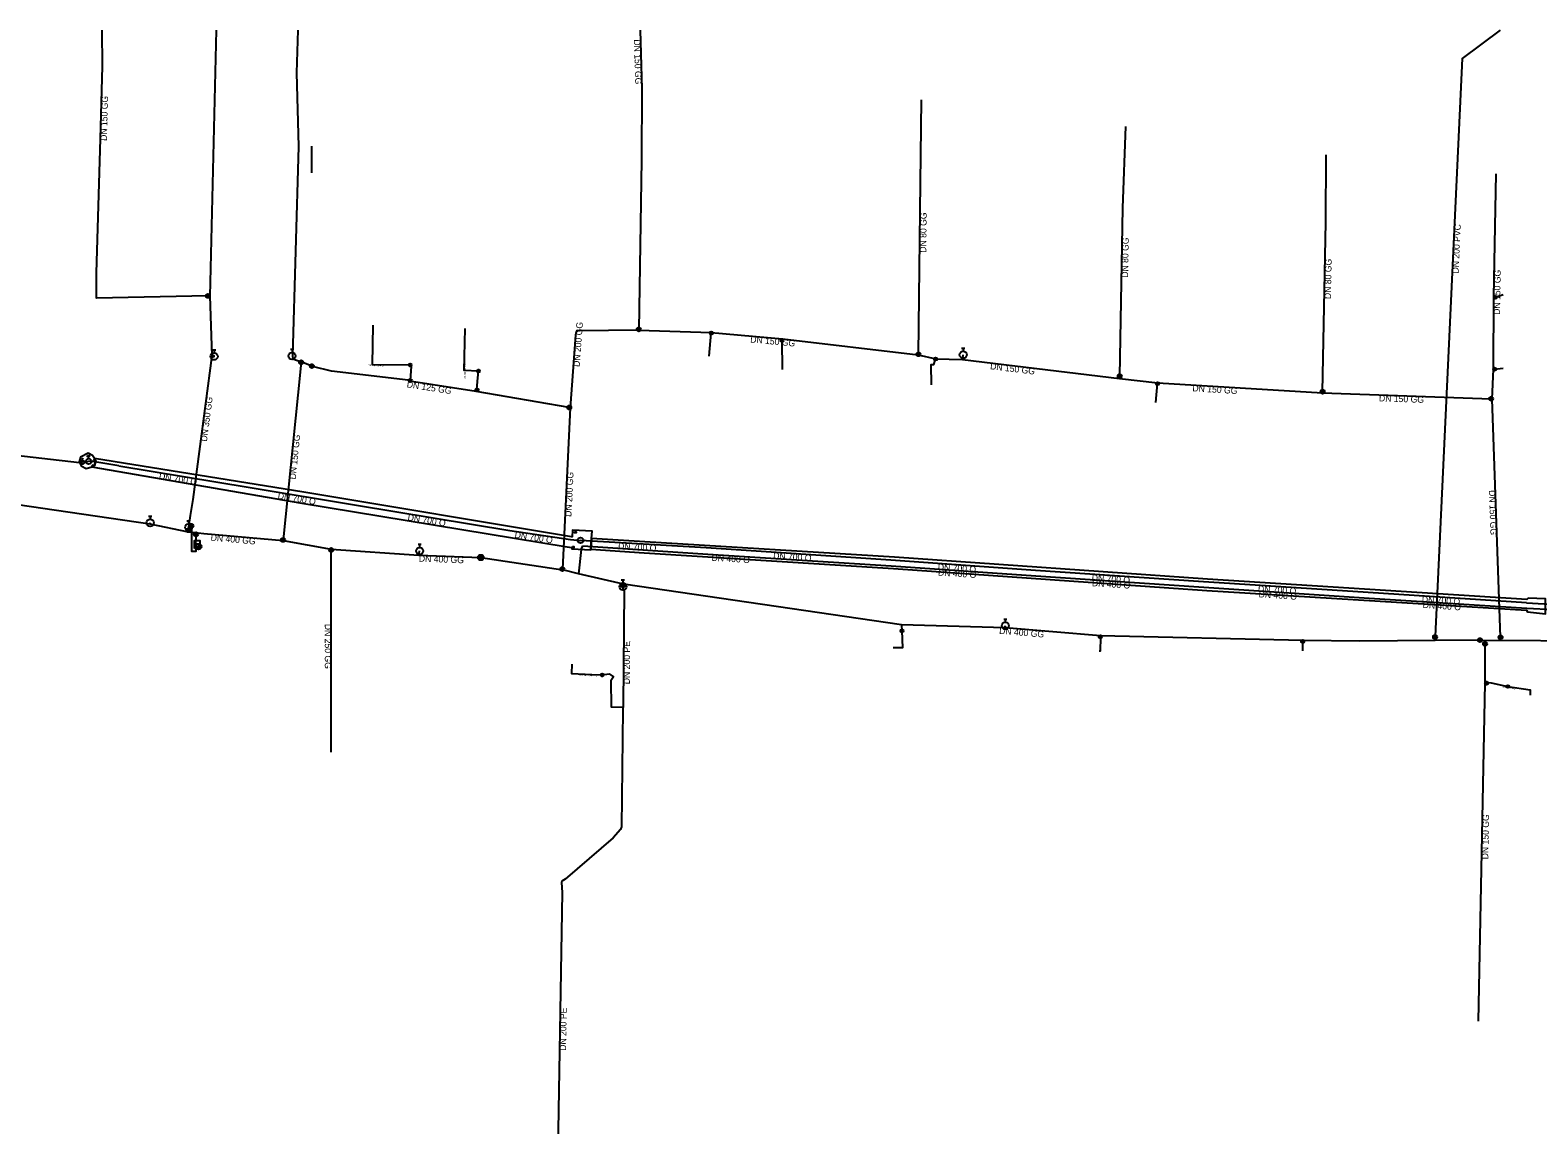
# Model space of a CAD drawing. Extents: x -451355 to -449353, y -1101368 to -1101089.
# Drawn here: x -450784.4 to -450409.1, y -1101364 to -1101089.2 of the extents above; entities that cross this region are included whole.
import ezdxf

# ---------------------------------------------------------------- set-up
doc = ezdxf.new("R2010")
doc.units = 0
for name, color, linetype in [('_hydrantova_odbocka_', 7, 'Continuous'), ('_kolektor_', 7, 'Continuous'), ('_pripojka_prevzato_z_dokumentace_', 7, 'Continuous'), ('_pripojka_priblizne_', 7, 'Continuous'), ('_sachta_voda_', 7, 'Continuous'), ('_voda_smvak_prevzato_z_dokumentace_', 7, 'Continuous'), ('_voda_smvak_priblizne_', 7, 'Continuous'), ('Default', 7, 'Continuous'), ('MoLevel 27', 7, 'Continuous'), ('MoLevel 28', 7, 'Continuous'), ('MoLevel 30', 7, 'Continuous'), ('MoLevel 38', 7, 'Continuous'), ('MoLevel 42', 7, 'Continuous'), ('MoLevel 46', 7, 'Continuous'), ('MoLevel 53', 7, 'Continuous'), ('MoLevel 55', 7, 'Continuous')]:
    doc.layers.add(name, color=color, linetype=linetype)

# ---------------------------------------------------------------- blocks, each defined once
blk = doc.blocks.new('_uzaver_')
at = {"layer": 'Default'}
for p, q in [((-0.000035, -0.000035), (0.000035, 0.000035)), ((0.000035, -0.000035), (-0.000035, 0.000035))]:
    blk.add_line(p, q, dxfattribs=at)
for radius in [0.00005, 0.0000025]:
    blk.add_circle((0, 0), radius, dxfattribs=at)
blk = doc.blocks.new('_uzaver_pripojka_')
at = {"layer": 'Default'}
for p, q in [((-0.000035, -0.000035), (0.000035, 0.000035)), ((0.000035, -0.000035), (-0.000035, 0.000035))]:
    blk.add_line(p, q, dxfattribs=at)
for radius in [0.00005, 0.0000025]:
    blk.add_circle((0, 0), radius, dxfattribs=at)
blk = doc.blocks.new('_hydrant_voda_')
at = {"layer": 'Default'}
for p, q in [((-0.000023, 0.000095), (0.000023, 0.000095)), ((0, 0.000095), (0, 0.00005))]:
    blk.add_line(p, q, dxfattribs=at)
blk.add_circle((0, 0), 0.00005, dxfattribs=at)
blk = doc.blocks.new('_vzdusnik_')
at = {"layer": 'Default'}
blk.add_line((0, 0.000095), (0.00001, 0.00008), dxfattribs=at)
blk.add_lwpolyline([(0, 0.00005), (0, 0.000095), (-0.00001, 0.00008)], dxfattribs=at)
blk.add_circle((0, 0), 0.00005, dxfattribs=at)
blk = doc.blocks.new('_sachta_voda_')
at = {"layer": 'Default'}
blk.add_circle((0, 0), 0.000035, dxfattribs=at)
blk = doc.blocks.new('_poklop_voda_')
at = {"layer": 'Default'}
blk.add_lwpolyline([(-0.00002, 0.000015), (0.00002, 0.000015), (0.00002, -0.000015), (-0.00002, -0.000015), (-0.00002, 0.000015)], dxfattribs=at)

msp = doc.modelspace()

# ---------------------------------------------------------------- linework, layer by layer
at = {"layer": '_hydrantova_odbocka_'}
msp.add_line((-450719.15, -1101170.31), (-450719.24, -1101170.31), dxfattribs=at)
for points in [[(-450738.63, -1101170.42), (-450738.92, -1101170.36), (-450739.22, -1101170.23)], [(-450552.32, -1101171.15), (-450552.27, -1101170.83), (-450552.17, -1101170.01)], [(-450754.63, -1101212.14), (-450754.55, -1101211.85), (-450754.55, -1101211.85)], [(-450687.71, -1101219.89), (-450687.6, -1101219.54), (-450687.47, -1101218.86)], [(-450541.73, -1101238), (-450541.69, -1101237.49), (-450541.69, -1101237.49), (-450541.69, -1101237.49), (-450541.69, -1101237.49), (-450541.69, -1101237.49), (-450541.69, -1101237.49), (-450541.69, -1101237.49), (-450541.69, -1101237.49), (-450541.69, -1101237.49)]]:
    msp.add_lwpolyline(points, dxfattribs=at)
at = {"layer": '_kolektor_'}
for points in [[(-450772.25, -1101196.65), (-450771.74, -1101197.69), (-450770.49, -1101198.33), (-450769.08, -1101197.93), (-450768.79, -1101197.48), (-450768.4, -1101197.55), (-450768.11, -1101196.3), (-450768.46, -1101196.22), (-450768.38, -1101195.87), (-450768.88, -1101195.09), (-450770.01, -1101194.53), (-450771.92, -1101195.51)], [(-450768.79, -1101197.48), (-450769.08, -1101197.93), (-450716.81, -1101206.92), (-450650.73, -1101217.85), (-450649.61, -1101217.97), (-450649.63, -1101218.32), (-450644.84, -1101218.6), (-450644.83, -1101218.45), (-450644.66, -1101215.78), (-450644.55, -1101213.95), (-450649.41, -1101213.66), (-450649.49, -1101215.33), (-450649.7, -1101215.3), (-450716.33, -1101204.25), (-450768.38, -1101195.87), (-450768.46, -1101196.22), (-450768.11, -1101196.3), (-450768.4, -1101197.55)], [(-450491.55, -1101228.73), (-450411.99, -1101233.64), (-450411.68, -1101234.01), (-450407.22, -1101234.54), (-450407.25, -1101230.81), (-450411.53, -1101230.63), (-450411.87, -1101230.98), (-450491.38, -1101225.92), (-450569.3, -1101220.42), (-450631.44, -1101216.56), (-450644.66, -1101215.78), (-450644.83, -1101218.45), (-450631.61, -1101219.35), (-450569.49, -1101223.22)]]:
    msp.add_lwpolyline(points, close=True, dxfattribs=at)
at = {"layer": '_pripojka_prevzato_z_dokumentace_'}
for p, q in [((-450673.03, -1101176.69), (-450672.8, -1101174.06)), ((-450644.57, -1101249.61), (-450642.07, -1101249.73)), ((-450642.07, -1101249.73), (-450640.26, -1101249.42))]:
    msp.add_line(p, q, dxfattribs=at)
for points in [[(-450420.08, -1101155.6), (-450419.72, -1101155.7), (-450417.76, -1101155)], [(-450699.15, -1101162.66), (-450699.31, -1101172.4), (-450689.86, -1101172.55)], [(-450672.8, -1101174.06), (-450676.4, -1101173.97), (-450676.14, -1101163.48)], [(-450615.37, -1101170.37), (-450614.89, -1101164.61), (-450614.89, -1101164.43)], [(-450597.15, -1101173.72), (-450597.26, -1101166.46), (-450597.15, -1101166.08)], [(-450689.86, -1101172.55), (-450689.6, -1101172.85), (-450689.8, -1101176.42), (-450689.98, -1101176.59)], [(-450420.18, -1101173.59), (-450419.91, -1101173.6), (-450417.8, -1101173.31)], [(-450673.42, -1101179.16), (-450673.21, -1101178.77), (-450673.03, -1101176.69)], [(-450504.21, -1101181.87), (-450503.79, -1101177.2), (-450503.74, -1101176.96)], [(-450567.54, -1101237.25), (-450567.41, -1101238.75), (-450567.27, -1101242.97), (-450569.61, -1101242.97)], [(-450518.01, -1101240.35), (-450518.04, -1101243.83), (-450518.32, -1101243.83)], [(-450518.02, -1101240.02), (-450518.01, -1101240.23), (-450518.01, -1101240.35)], [(-450649.6, -1101247.04), (-450649.67, -1101249.36), (-450644.57, -1101249.61)], [(-450640.26, -1101249.42), (-450639.18, -1101250.22), (-450639.85, -1101251.21), (-450639.82, -1101257.7), (-450636.84, -1101257.77)], [(-450422.26, -1101251.79), (-450421.91, -1101251.8), (-450421.46, -1101251.76), (-450421.29, -1101251.63), (-450420.79, -1101251.73), (-450416.58, -1101252.59)], [(-450416.58, -1101252.59), (-450411.01, -1101253.41), (-450411.01, -1101254.73)]]:
    msp.add_lwpolyline(points, dxfattribs=at)
at = {"layer": '_pripojka_priblizne_'}
msp.add_line((-450714.39, -1101118.07), (-450714.43, -1101124.7), dxfattribs=at)
for points in [[(-450560.03, -1101177.51), (-450560.16, -1101172.47), (-450559.46, -1101172.44), (-450559.03, -1101171.08), (-450558.99, -1101170.99)], [(-450467.67, -1101243.73), (-450467.67, -1101241.38), (-450467.67, -1101241.15)]]:
    msp.add_lwpolyline(points, dxfattribs=at)
at = {"layer": '_sachta_voda_'}
msp.add_lwpolyline([(-450743.53, -1101218.21), (-450743.55, -1101216.27), (-450742.22, -1101216.25), (-450742.2, -1101218.19)], close=True, dxfattribs=at)
at = {"layer": '_voda_smvak_prevzato_z_dokumentace_'}
for p, q in [((-450738.1, -1101089.19), (-450739.7, -1101155.45)), ((-450632.92, -1101163.69), (-450632.91, -1101163.92)), ((-450714.3, -1101172.84), (-450716.96, -1101171.76)), ((-450563.41, -1101170.07), (-450563.31, -1101169.9)), ((-450513.29, -1101175.94), (-450513.21, -1101175.34)), ((-450462.74, -1101179.5), (-450462.71, -1101179.2)), ((-450717.8, -1101180.04), (-450721.48, -1101216.12)), ((-450462.74, -1101179.5), (-450420.76, -1101180.97)), ((-450420.76, -1101180.97), (-450420.51, -1101181.04)), ((-450418.41, -1101240.35), (-450420.51, -1101181.04)), ((-450649.98, -1101183.21), (-450651.94, -1101223.38)), ((-450649.98, -1101183.21), (-450650.22, -1101183.14)), ((-450769.33, -1101196.48), (-450769.86, -1101196.56)), ((-450762.33, -1101197.68), (-450769.33, -1101196.48)), ((-450762.33, -1101197.68), (-450729.67, -1101203.08)), ((-450729.67, -1101203.08), (-450703.2, -1101207.49)), ((-450703.2, -1101207.49), (-450664.99, -1101213.77)), ((-450744.99, -1101213.01), (-450745.08, -1101213.69)), ((-450744.89, -1101212.23), (-450744.99, -1101213.01)), ((-450744.56, -1101210.06), (-450744.89, -1101212.23)), ((-450745.08, -1101213.69), (-450745.13, -1101214.06)), ((-450745.13, -1101214.06), (-450743.61, -1101214.25)), ((-450743.61, -1101214.25), (-450743.1, -1101214.3)), ((-450743.14, -1101214.72), (-450743.1, -1101214.3)), ((-450743.1, -1101214.3), (-450742.6, -1101214.36)), ((-450721.48, -1101216.12), (-450721.45, -1101216.29)), ((-450721.45, -1101216.29), (-450709.53, -1101218.38)), ((-450664.99, -1101213.77), (-450649.94, -1101216.04)), ((-450649.94, -1101216.04), (-450647.41, -1101216.23)), ((-450616.13, -1101218.09), (-450647.41, -1101216.23)), ((-450709.49, -1101218.6), (-450709.53, -1101218.38)), ((-450709.46, -1101268.98), (-450709.49, -1101218.6)), ((-450672.25, -1101220.49), (-450651.86, -1101223.59)), ((-450647.26, -1101218.46), (-450646.84, -1101217.61)), ((-450570.19, -1101221.16), (-450616.13, -1101218.09)), ((-450651.94, -1101223.38), (-450651.86, -1101223.59)), ((-450647.91, -1101224.54), (-450651.86, -1101223.59)), ((-450534.15, -1101223.76), (-450570.19, -1101221.16)), ((-450570.14, -1101222.54), (-450534.08, -1101225.05)), ((-450493.56, -1101226.5), (-450534.15, -1101223.76)), ((-450636.76, -1101227.11), (-450647.91, -1101224.54)), ((-450636.86, -1101227.43), (-450636.87, -1101227.73)), ((-450636.86, -1101227.43), (-450636.76, -1101227.11)), ((-450534.08, -1101225.05), (-450493.52, -1101227.82)), ((-450451.4, -1101229.18), (-450493.56, -1101226.5)), ((-450493.52, -1101227.82), (-450451.11, -1101230.59)), ((-450411.98, -1101231.78), (-450451.4, -1101229.18)), ((-450451.11, -1101230.59), (-450411.85, -1101233.11)), ((-450411.98, -1101231.78), (-450404.62, -1101232.17)), ((-450411.85, -1101233.11), (-450405.3, -1101233.46)), ((-450434.72, -1101240.26), (-450434.73, -1101241.16)), ((-450423.55, -1101241.06), (-450434.73, -1101241.16)), ((-450422.22, -1101241.23), (-450423.55, -1101241.06)), ((-450422.28, -1101242), (-450422.22, -1101241.23)), ((-450418.57, -1101241.13), (-450422.22, -1101241.23)), ((-450418.41, -1101240.35), (-450418.57, -1101241.13))]:
    msp.add_line(p, q, dxfattribs=at)
for points in [[(-450740.19, -1101155.37), (-450767.9, -1101155.91), (-450767.89, -1101149.61), (-450766.92, -1101116.23), (-450766.43, -1101098.18), (-450766.52, -1101089.19)], [(-450717.79, -1101089.19), (-450718.15, -1101099.81), (-450717.61, -1101118.13), (-450719.15, -1101170.31), (-450719.02, -1101170.99), (-450716.96, -1101171.76)], [(-450632.6, -1101089.19), (-450632.15, -1101103.82), (-450632.25, -1101121.58), (-450632.92, -1101163.69)], [(-450418.51, -1101089.19), (-450427.99, -1101096.23), (-450434.67, -1101240.1), (-450434.72, -1101240.26)], [(-450563.31, -1101169.9), (-450562.76, -1101127.2), (-450562.58, -1101106.55)], [(-450513.21, -1101175.34), (-450512.41, -1101133.42), (-450511.68, -1101113.18)], [(-450462.71, -1101179.2), (-450461.88, -1101136.96), (-450461.86, -1101120.21)], [(-450420.51, -1101181.04), (-450420.18, -1101173.59), (-450420.08, -1101155.6), (-450419.52, -1101125)], [(-450739.7, -1101155.45), (-450739.22, -1101170.23), (-450743.94, -1101206.05), (-450744.56, -1101210.06)], [(-450739.7, -1101155.45), (-450740.01, -1101155.36), (-450740.19, -1101155.37)], [(-450632.91, -1101163.92), (-450648.05, -1101164.05), (-450648.47, -1101164.33), (-450648.67, -1101165.11), (-450649.98, -1101183.21)], [(-450632.91, -1101163.92), (-450614.89, -1101164.43), (-450597.15, -1101166.08), (-450563.41, -1101170.07)], [(-450563.41, -1101170.07), (-450558.99, -1101170.99), (-450552.32, -1101171.15), (-450513.29, -1101175.94)], [(-450650.22, -1101183.14), (-450673.42, -1101179.16), (-450689.98, -1101176.59), (-450690.29, -1101176.36), (-450709.42, -1101174.09), (-450714.12, -1101172.91), (-450714.3, -1101172.84)], [(-450513.29, -1101175.94), (-450503.74, -1101176.96), (-450462.74, -1101179.5)], [(-451068.8, -1101188.58), (-451050.3, -1101190.14), (-451032.45, -1101189.7), (-450997.22, -1101189.02), (-450996.11, -1101185.36), (-450995.63, -1101185.21), (-450938.03, -1101181.08), (-450926.89, -1101179.79), (-450899.38, -1101182.22), (-450888.28, -1101183.45), (-450772.13, -1101196.87)], [(-451068.59, -1101187.08), (-451038.12, -1101189.24), (-451006.24, -1101186.52), (-450999.94, -1101184.64), (-450989.76, -1101181.39), (-450987.33, -1101181.88), (-450981.7, -1101184.05), (-450958.04, -1101193.09), (-450953.39, -1101195.36), (-450948.09, -1101195.61), (-450932.19, -1101196.67), (-450910.27, -1101194.8), (-450873.74, -1101196.81), (-450845.59, -1101199.31), (-450831.24, -1101200.86), (-450754.63, -1101212.14), (-450745.13, -1101214.06)], [(-450769.86, -1101196.56), (-450771.41, -1101196.77), (-450772.13, -1101196.87)], [(-450744.89, -1101212.23), (-450744.35, -1101212.29), (-450744.28, -1101212.3), (-450744.28, -1101212.6)], [(-450744.28, -1101212.6), (-450744.28, -1101212.91), (-450744.23, -1101218.91), (-450743.13, -1101218.89), (-450743.14, -1101217.84), (-450743.15, -1101216.87), (-450743.14, -1101215.31), (-450743.14, -1101215.16), (-450743.14, -1101214.72)], [(-450742.6, -1101214.36), (-450741.19, -1101214.53), (-450721.45, -1101216.29)], [(-450709.53, -1101218.38), (-450687.71, -1101219.89), (-450672.25, -1101220.49)], [(-450646.84, -1101217.61), (-450615.77, -1101219.62), (-450570.14, -1101222.54)], [(-450636.87, -1101227.73), (-450636.9, -1101228.29), (-450636.58, -1101228.63), (-450636.8, -1101257.25), (-450636.84, -1101257.77), (-450636.87, -1101258.09), (-450636.89, -1101258.32), (-450637.25, -1101287.55), (-450637.49, -1101288.19), (-450639.32, -1101290.25), (-450651.29, -1101300.57), (-450652.05, -1101301.1), (-450652.19, -1101301.44), (-450651.97, -1101303.91), (-450652.99, -1101363.06), (-450652.96, -1101363.98)], [(-450434.73, -1101241.16), (-450453.43, -1101241.33), (-450467.67, -1101241.15), (-450518.02, -1101240.02), (-450541.73, -1101238), (-450567.54, -1101237.25), (-450636.76, -1101227.11)], [(-450423.92, -1101335.92), (-450422.26, -1101251.79), (-450422.28, -1101242)], [(-450254.28, -1101242.82), (-450286.68, -1101241.85), (-450297.69, -1101242.48), (-450346.86, -1101241.73), (-450398.26, -1101241.29), (-450418.57, -1101241.13)]]:
    msp.add_lwpolyline(points, dxfattribs=at)
at = {"layer": '_voda_smvak_priblizne_'}
for p, q in [((-450716.96, -1101171.76), (-450716.97, -1101171.88)), ((-450716.97, -1101171.88), (-450717.8, -1101180.04)), ((-450647.26, -1101218.46), (-450647.91, -1101224.54))]:
    msp.add_line(p, q, dxfattribs=at)

# ---------------------------------------------------------------- block references
at = {"layer": 'MoLevel 27'}
for p, xscale, yscale, rotation in [((-450740.19, -1101155.37), 9999.999999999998, 10000.000000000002, -178.87811465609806), ((-450632.92, -1101163.69), 10000, 10000, 89.062026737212), ((-450716.97, -1101171.88), 10000, 9999.999999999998, -95.70850350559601), ((-450563.31, -1101169.9), 10000, 10000, 89.2417061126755), ((-450714.3, -1101172.84), 10000, 10000, -15.146232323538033), ((-450513.21, -1101175.34), 10000, 10000, 88.8816299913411), ((-450462.71, -1101179.2), 10000, 9999.999999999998, 88.8498902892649), ((-450650.22, -1101183.14), 10000.000000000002, 10000, 170.26785673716), ((-450420.76, -1101180.97), 10000, 10000, 178.00107825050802), ((-450744.28, -1101212.6), 10000, 9999.999999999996, 89.88976137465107), ((-450745.08, -1101213.69), 10000.000000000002, 9999.999999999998, -92.86335845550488), ((-450743.14, -1101214.72), 9999.999999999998, 10000, 88.58725866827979), ((-450721.48, -1101216.12), 10000.000000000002, 10000, 84.1730661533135), ((-450709.49, -1101218.6), 10000, 10000.000000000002, -89.95797231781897), ((-450651.94, -1101223.38), 10000, 10000, 87.1858259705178), ((-450636.86, -1101227.43), 10000.000000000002, 10000, -89.72007112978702), ((-450541.73, -1101238), 5000, 5000, -4.869618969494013), ((-450434.72, -1101240.26), 10000, 9999.999999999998, 85.2942290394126), ((-450423.55, -1101241.06), 10000.000000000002, 9999.999999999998, -179.47708048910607), ((-450422.28, -1101242), 10000, 10000, 85.5119034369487), ((-450418.41, -1101240.35), 10000, 10000, 92.0271921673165)]:
    msp.add_blockref('_uzaver_', p, dxfattribs=dict(at, xscale=xscale, yscale=yscale, rotation=rotation))
for p, xscale, yscale in [((-450738.92, -1101170.36), 5000, 5000), ((-450552.27, -1101170.83), 5000, 5000), ((-450672.25, -1101220.49), 10000, 10000)]:
    msp.add_blockref('_uzaver_', p, dxfattribs=dict(at, xscale=xscale, yscale=yscale))
at = {"layer": 'MoLevel 28', "xscale": 17636.68430335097, "yscale": 17636.68430335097}
for p in [(-450738.63, -1101170.42), (-450719.24, -1101170.31), (-450552.17, -1101170.01), (-450754.55, -1101211.85), (-450744.98, -1101213.01), (-450687.47, -1101218.86), (-450636.87, -1101227.73), (-450541.69, -1101237.49)]:
    msp.add_blockref('_hydrant_voda_', p, dxfattribs=at)
at = {"layer": 'MoLevel 30'}
for p, xscale, yscale in [((-450689.86, -1101172.55), 10000, 10000), ((-450672.8, -1101174.06), 10000, 10000), ((-450769.86, -1101196.56), 20000, 20000), ((-450647.41, -1101216.23), 20000, 20000), ((-450742.49, -1101217.76), 20000, 20000), ((-450672.25, -1101220.49), 20000, 20000), ((-450642.07, -1101249.73), 10000, 10000), ((-450416.58, -1101252.59), 10000, 10000)]:
    msp.add_blockref('_sachta_voda_', p, dxfattribs=dict(at, xscale=xscale, yscale=yscale))
at = {"layer": 'MoLevel 38', "xscale": 10000, "yscale": 10000}
msp.add_blockref('_vzdusnik_', (-450771.41, -1101196.77), dxfattribs=at)
at = {"layer": 'MoLevel 42', "xscale": 10000, "yscale": 10000}
for p in [(-450769.95, -1101195.26), (-450648.69, -1101214.23), (-450742.49, -1101217.76), (-450649.25, -1101217.91)]:
    msp.add_blockref('_poklop_voda_', p, dxfattribs=at)
at = {"layer": 'MoLevel 53', "xscale": 7999.999999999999, "yscale": 7999.999999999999}
for p in [(-450419.72, -1101155.7), (-450614.89, -1101164.61), (-450597.26, -1101166.46), (-450559.03, -1101171.08), (-450419.91, -1101173.6), (-450689.8, -1101176.42), (-450673.21, -1101178.77), (-450503.79, -1101177.2), (-450567.41, -1101238.75), (-450518.01, -1101240.23), (-450467.67, -1101241.38), (-450421.91, -1101251.8)]:
    msp.add_blockref('_uzaver_pripojka_', p, dxfattribs=at)

# ---------------------------------------------------------------- texts
at = {"layer": 'MoLevel 46'}
for s, rotation, p in [('DN 150 GG', 271.7701, (-450634.14, -1101091.51)), ('DN 150 GG', 88.445, (-450765.33, -1101116.78)), ('DN 80 GG', 89.262, (-450561.38, -1101144.61)), ('DN 200 PVC', 87.3416, (-450428.87, -1101149.8)), ('DN 80 GG', 88.9067, (-450511.14, -1101150.85)), ('DN 80 GG', 88.8743, (-450460.65, -1101156.15)), ('DN 150 GG', 88.9516, (-450418.56, -1101160.08)), ('DN 200 GG', 85.8604, (-450647.64, -1101173.08)), ('DN 150 GG', 354.6862, (-450605.23, -1101166.94)), ('DN 150 GG', 353.0033, (-450545.53, -1101173.6)), ('DN 125 GG', 351.1785, (-450690.76, -1101178.09)), ('DN 150 GG', 356.455, (-450495.15, -1101179.1)), ('DN 350 GG', 82.4934, (-450740.43, -1101191.7)), ('DN 150 GG', 357.9945, (-450448.7, -1101181.6)), ('DN 150 GG', 84.182, (-450718.34, -1101201.1)), ('DN 700 O', 350.6117, (-450752.44, -1101200.94)), ('DN 200 GG', 87.2066, (-450649.7, -1101210.4)), ('DN 700 O', 350.5412, (-450722.88, -1101205.84)), ('DN 150 GG', 272.0278, (-450421.31, -1101203.73)), ('DN 700 O', 350.6666, (-450690.54, -1101211.2)), ('DN 400 GG', 354.905, (-450739.54, -1101216.26)), ('DN 700 O', 351.4227, (-450663.9, -1101215.56)), ('DN 700 O', 356.597, (-450638.12, -1101218.39)), ('DN 400 GG', 357.7775, (-450687.69, -1101221.5)), ('DN 400 O', 356.3385, (-450614.85, -1101221.29)), ('DN 700 O', 356.1768, (-450599.52, -1101220.81)), ('DN 700 O', 355.8737, (-450558.54, -1101223.61)), ('DN 400 O', 356.0183, (-450558.47, -1101224.96)), ('DN 700 O', 356.1381, (-450520.22, -1101226.31)), ('DN 400 O', 356.0931, (-450520.16, -1101227.61)), ('DN 700 O', 356.3628, (-450478.84, -1101229.04)), ('DN 400 O', 356.2631, (-450478.67, -1101230.4)), ('DN 700 O', 356.2264, (-450438.05, -1101231.67)), ('DN 400 O', 356.3274, (-450437.84, -1101233.05)), ('DN 250 GG', 270.0341, (-450711.08, -1101237)), ('DN 400 GG', 355.1304, (-450543.27, -1101239.48)), ('DN 200 PE', 89.5596, (-450635.15, -1101252.04)), ('DN 150 GG', 88.8676, (-450421.48, -1101295.64)), ('DN 200 PE', 89.0121, (-450651.04, -1101343.31))]:
    msp.add_text(s, height=1.605, rotation=rotation, dxfattribs=at).set_placement(p)
at = {"layer": 'MoLevel 55'}
for s, rotation, p in [('DN 40 - 6/4 O', 359.0906, (-450700.32, -1101172.84)), ("DN 50 - 2'' PE", 88.6183, (-450675.99, -1101176.06)), ("DN 32 - 5/4'' PE", 357.2128, (-450647.79, -1101249.91)), ('DN 100 GG', 351.6252, (-450417.99, -1101252.84))]:
    msp.add_text(s, height=0.455, rotation=rotation, dxfattribs=at).set_placement(p)

doc.saveas('drawing.dxf')
